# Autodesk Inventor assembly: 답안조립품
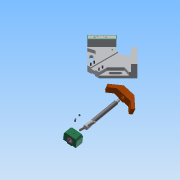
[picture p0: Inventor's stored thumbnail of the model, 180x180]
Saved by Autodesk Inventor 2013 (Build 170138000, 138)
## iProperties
Created: 2019-04
Part Number: 답안조립품
Document SubType Name: Assembly
Designer: Administrator
Author: Administrator
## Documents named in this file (11)
- C:\Users\Administrator\Desktop\490407V1016\답안조립품.iam
- C:\Users\Administrator\Desktop\490407V1016\베이스.ipt
- C:\Users\Administrator\Desktop\490407V1016\리드스크류.ipt
- C:\Users\Administrator\Desktop\490407V1016\멈춤나사 M4x5.ipt
- C:\Users\Administrator\Desktop\490407V1016\멈춤나사 M4x10.ipt
- C:\Users\Administrator\Desktop\490407V1016\볼트 M4x16.ipt
- C:\Users\Administrator\Desktop\490407V1016\부시.ipt
- C:\Users\Administrator\Desktop\490407V1016\서포트.ipt
- C:\Users\Administrator\Desktop\490407V1016\조.ipt
- C:\Users\Administrator\Desktop\490407V1016\평행 핀 2.5x24.ipt
- C:\Users\Administrator\Desktop\490407V1016\핸들.ipt
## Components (1 placed, 1 different names)
1. 핸들:1
